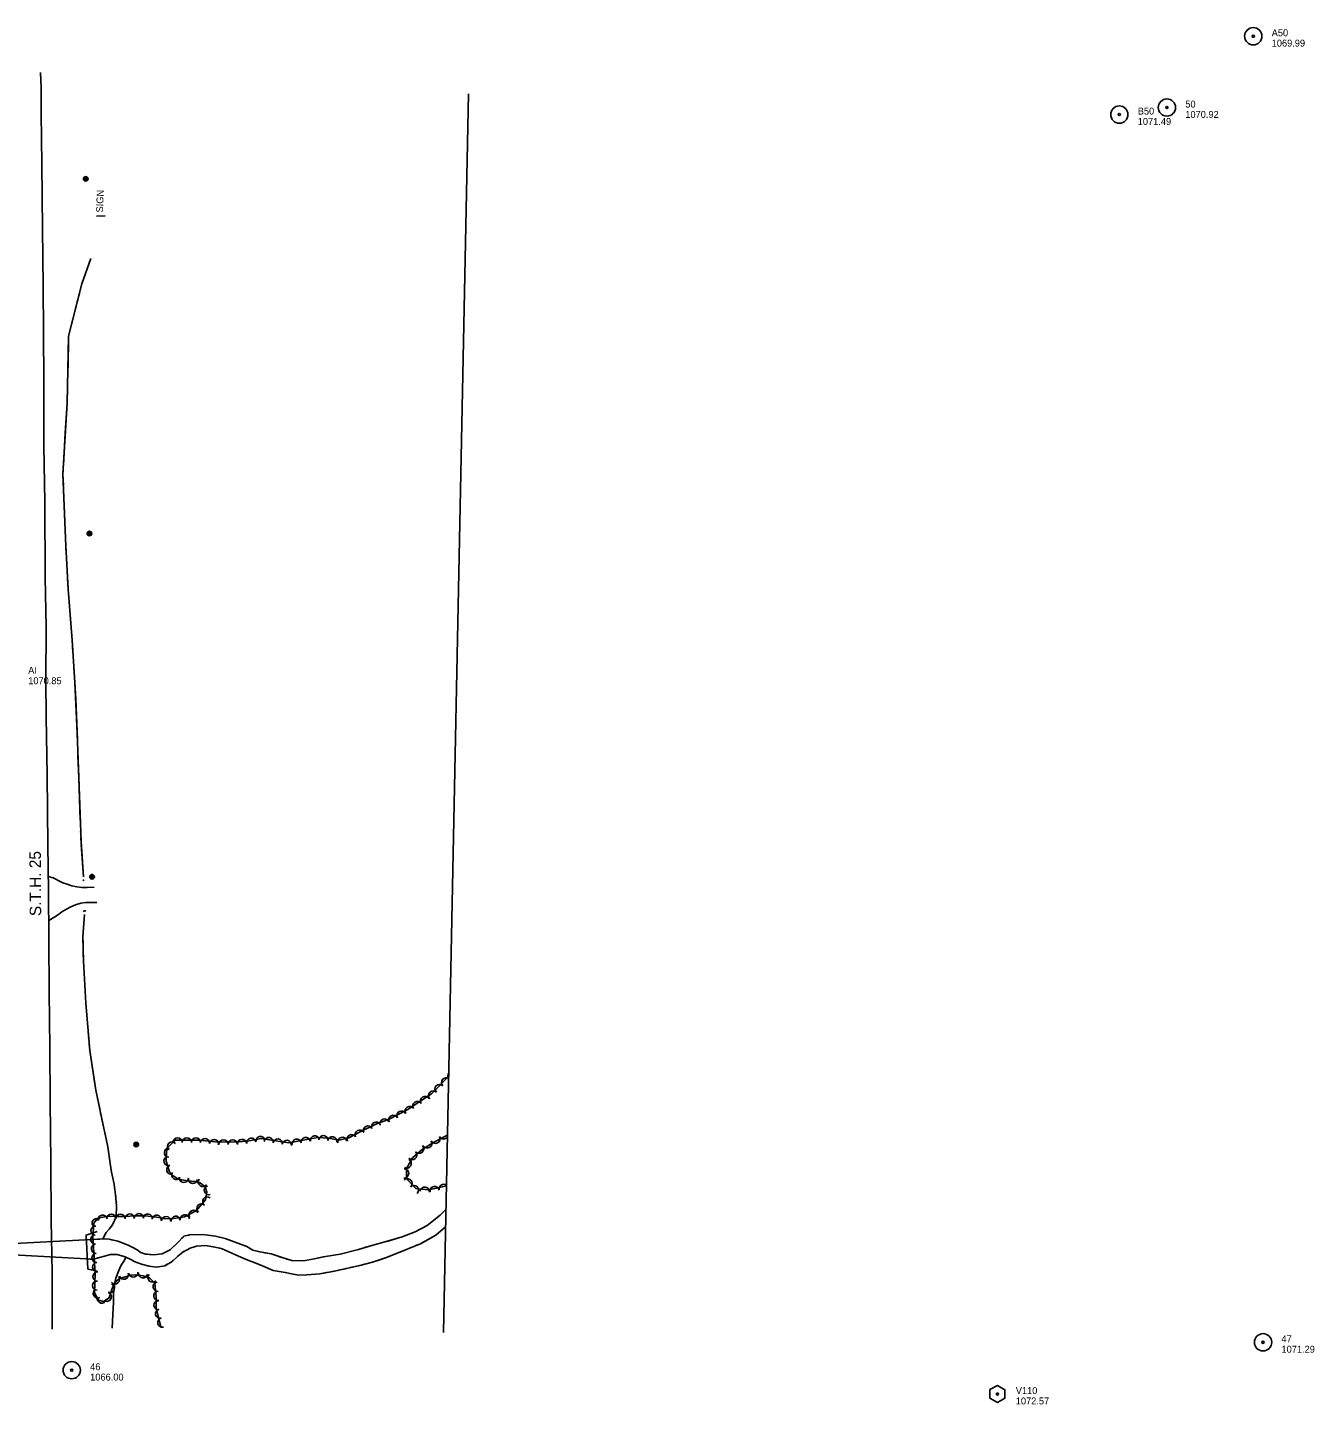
# Model space of a CAD drawing. Extents: x 296471 to 298842, y 32694 to 33905.
# Drawn here: x 297724 to 298842, y 32694 to 33889 of the extents above; entities that cross this region are included whole.
import ezdxf

# ---------------------------------------------------------------- set-up
doc = ezdxf.new("R2010")
doc.units = 0
for name, color, linetype in [('Level 11', 7, 'Continuous'), ('Level 14', 7, 'Continuous'), ('Level 15', 7, 'Continuous'), ('Level 17', 7, 'Continuous'), ('Level 18', 7, 'Continuous'), ('Level 19', 7, 'Continuous'), ('Level 4', 7, 'Continuous'), ('Level 5', 7, 'Continuous'), ('Level 6', 7, 'Continuous')]:
    doc.layers.add(name, color=color, linetype=linetype)

msp = doc.modelspace()

# ---------------------------------------------------------------- linework, layer by layer
at = {"layer": 'Level 11'}
msp.add_lwpolyline([(297745.7, 32759.5), (297745.6, 32808.7), (297744.8, 32853.7), (297744.4, 32904), (297743.9, 32957.3), (297743.6, 33003.6), (297743, 33052.3), (297742.7, 33098.1), (297742.4, 33139.8), (297741.7, 33179.5), (297741.4, 33240.2), (297740.4, 33290.9), (297740, 33322.6), (297740.3, 33368.7), (297739.6, 33412), (297739.2, 33477.2), (297738.3, 33526.1), (297738.3, 33583.2), (297737.8, 33665.2), (297737.1, 33714.6), (297736.6, 33770.6), (297736.1, 33814.6), (297736, 33837.2), (297735.4, 33850.4)], dxfattribs=at)
at = {"layer": 'Level 14'}
msp.add_line((297784.2, 33725.6), (297791.7, 33725.8), dxfattribs=at)
for centre, radius in [((297774.7, 33758), 2.02), ((297774.7, 33758), 1.52), ((297774.8, 33758), 1.01), ((297774.8, 33758.1), 0.502), ((297777.9, 33450.1), 2.02), ((297777.9, 33450.1), 1.52), ((297777.9, 33450.1), 1.01), ((297777.9, 33450.1), 0.502), ((297780.2, 33152.1), 2.02), ((297780.2, 33152.1), 1.52), ((297780.3, 33152.1), 1.01), ((297780.2, 33152.1), 0.502), ((297818.6, 32919.7), 2.02), ((297818.6, 32919.7), 1.52), ((297818.6, 32919.7), 1.01), ((297818.6, 32919.7), 0.502)]:
    msp.add_circle(centre, radius, dxfattribs=at)
at = {"layer": 'Level 15'}
msp.add_lwpolyline([(297784, 32809.9), (297776.7, 32811.6), (297775, 32841.1), (297784.6, 32844.2)], dxfattribs=at)
for centre, radius, start, end in [((297772.8, 33150), 0.795, 220.5288, 326.7683), ((297773.8, 33121.2), 1.37, 45.8398, 152.0794)]:
    msp.add_arc(centre, radius, start, end, dxfattribs=at)
at = {"layer": 'Level 17'}
for points in [[(297782.2, 33143.2), (297776.1, 33142.7), (297771.3, 33142.9), (297767.1, 33143.4), (297762.7, 33144.4), (297758.5, 33145.7), (297755, 33146.9), (297751.9, 33148.2), (297748.2, 33150.2), (297746.5, 33151.3), (297742.2, 33152.5)], [(297742.6, 33114.2), (297747.9, 33117.3), (297751, 33119.3), (297753.9, 33121.7), (297757.6, 33123.8), (297761.8, 33126), (297765.8, 33127.8), (297770.6, 33129.1), (297774.9, 33129.7), (297779.2, 33129.9), (297782.5, 33129.9), (297784.4, 33129.7)]]:
    msp.add_lwpolyline(points, dxfattribs=at)
at = {"layer": 'Level 18'}
for points in [[(298089.9, 32979), (298074.9, 32963.6), (298053.8, 32949.7), (298038.3, 32941.7), (298026.7, 32937.5), (298012.9, 32930.8), (298003.2, 32925.5), (297994.6, 32923.5), (297985.7, 32925.2), (297976.4, 32925.8), (297963.5, 32923.5), (297951.2, 32921.3), (297939.8, 32922.9), (297927.2, 32925), (297915.2, 32922.7), (297906.6, 32921.9), (297890, 32921.7), (297873.5, 32923.6), (297852.6, 32923.6), (297845.1, 32916.4), (297844.5, 32905.1), (297847.4, 32895.9), (297850.8, 32892.5), (297854.6, 32889.9), (297857.8, 32888.9), (297863.8, 32888.3), (297869.6, 32887.6), (297874, 32886.3), (297878.4, 32883), (297880, 32878.3), (297878.8, 32871.7), (297870.6, 32862), (297860.6, 32856.8), (297849.2, 32855.1), (297842.5, 32855.4), (297836.3, 32856.6), (297826.3, 32857.8), (297818.8, 32857.7), (297807.6, 32857.3), (297800.5, 32857.3), (297793.8, 32857.4), (297785.3, 32855.9), (297781.7, 32851.4), (297780.8, 32839.4), (297782, 32821.4), (297783, 32807.7), (297782.7, 32799.1), (297782.5, 32791), (297785.8, 32784.5), (297790.2, 32783.5), (297795, 32786.6), (297797.5, 32793.9), (297799.8, 32799.7), (297804.2, 32803.3), (297809.1, 32804.9), (297813.9, 32806.2), (297818.2, 32806.6), (297824.6, 32805.7), (297830, 32803.9), (297834.8, 32799.4), (297835.1, 32796.2), (297835.8, 32787.1), (297835.9, 32777.5), (297840.3, 32760.7)], [(298088, 32884), (298087.8, 32883.9), (298080.8, 32882.2), (298072, 32880.5), (298061.4, 32881.5), (298053.2, 32889.9), (298053.3, 32898.8), (298058.5, 32908.1), (298067.2, 32915.8), (298078.3, 32922.3), (298085.4, 32926), (298088.9, 32927.9)]]:
    msp.add_lwpolyline(points, dxfattribs=at)
for centre, radius, start, end in [((298093.1, 32979.4), 3.99, 142.7947, 214.8848), ((298082, 32967.9), 3.99, 45.8286, 225.8133), ((298087.6, 32973.6), 3.99, 55.0667, 225.8133), ((298062.7, 32953.1), 3.99, 33.3523, 213.337), ((298069.4, 32957.5), 3.99, 33.3523, 213.337), ((298076.4, 32962.2), 3.99, 45.8286, 225.8133), ((298041.8, 32941.1), 3.99, 27.3914, 207.3761), ((298048.9, 32944.8), 3.99, 27.3914, 207.3761), ((298056.1, 32948.7), 3.99, 33.3523, 213.337), ((298012.6, 32928.3), 3.99, 28.6819, 208.6666), ((298019.7, 32931.8), 3.99, 25.7904, 205.7751), ((298026.9, 32935.2), 3.99, 25.7904, 205.7751), ((298034.2, 32937.9), 3.99, 19.8828, 199.8675), ((297849.7, 32917.9), 3.99, 43.7975, 223.7821), ((297854.5, 32921.5), 3.99, 359.9336, 179.9183), ((297862.5, 32921.5), 3.99, 359.9336, 179.9183), ((297870.5, 32921.5), 3.99, 359.9336, 179.9183), ((297878.2, 32920.9), 3.99, 353.5497, 173.5344), ((297886.2, 32920), 3.99, 353.5497, 173.5344), ((297894.4, 32919.7), 3.99, 0.8438, 180.8284), ((297902.4, 32919.8), 3.99, 0.8438, 180.8284), ((297910.5, 32920.2), 3.99, 5.1973, 185.182), ((297918.6, 32921.2), 3.99, 10.8716, 190.8563), ((297926.5, 32922.7), 3.99, 10.8716, 190.8563), ((297933.6, 32921.8), 3.99, 350.5439, 170.5285), ((297941.5, 32920.6), 3.99, 351.7578, 171.7425), ((297949.4, 32919.4), 3.99, 351.7578, 171.7425), ((297958, 32920.4), 3.99, 10.0225, 190.0072), ((297965.8, 32921.8), 3.99, 10.3728, 190.3575), ((297973.7, 32923.2), 3.99, 10.3728, 190.3575), ((297981.1, 32923.4), 3.99, 356.1826, 176.1672), ((297988.8, 32922.5), 3.99, 349.1535, 169.1382), ((297997.5, 32922), 3.99, 13.0293, 193.014), ((298005.6, 32924.4), 3.99, 28.6819, 208.6666), ((298064.2, 32916), 4.06, 221.7032, 41.6879), ((298071.3, 32920.7), 4.06, 210.3064, 30.2911), ((298078.4, 32924.7), 4.06, 207.6497, 27.6344), ((298085.6, 32928.5), 4.06, 208.3577, 322.9908), ((297846.6, 32905.4), 3.99, 107.5699, 287.5546), ((297847, 32912.6), 3.99, 86.7553, 266.7399), ((298053.4, 32903.2), 4.06, 240.7011, 60.6858), ((298058.2, 32910.6), 4.06, 221.7032, 41.6879), ((297849, 32897.8), 3.99, 107.5699, 287.5546), ((297853.5, 32893.2), 3.99, 145.2965, 325.2812), ((298051.1, 32894.6), 4.06, 268.8817, 88.8664), ((297859.9, 32890.8), 3.99, 174.0309, 354.0156), ((297867.8, 32889.9), 3.99, 173.2863, 353.271), ((297876.4, 32887.2), 3.99, 142.6731, 322.6577), ((297881.6, 32880), 3.99, 108.4864, 288.471), ((298054.1, 32886), 4.06, 314.4349, 134.4196), ((298059.7, 32880.2), 4.06, 314.4349, 134.4196), ((298069.1, 32878.7), 4.06, 354.5144, 174.4991), ((298077.7, 32879.4), 4.06, 10.8715, 190.8562), ((298085.7, 32881.2), 4.06, 55.6508, 193.7913), ((297880.3, 32870.3), 3.99, 50.0078, 229.9925), ((297796.9, 32855.3), 3.99, 358.6336, 178.6183), ((297804.9, 32855.2), 3.99, 0.1213, 180.1059), ((297813, 32855.4), 3.99, 2.3923, 182.377), ((297820.9, 32855.7), 3.99, 0.2737, 180.2584), ((297828.6, 32855.4), 3.99, 353.3787, 173.3634), ((297860.8, 32854.7), 3.99, 8.6229, 188.6075), ((297868.5, 32858.6), 3.99, 27.5153, 207.4999), ((297875.2, 32864.1), 3.99, 50.0078, 229.9925), ((297783.3, 32844.9), 3.99, 85.9315, 265.9162), ((297784.3, 32851.4), 3.99, 51.4537, 231.4383), ((297789.4, 32854.5), 3.99, 10.003, 189.9877), ((297836.4, 32854.5), 3.99, 348.5183, 168.503), ((297844.5, 32853.2), 3.99, 357.4393, 177.424), ((297852.9, 32853.5), 3.99, 8.6229, 188.6075), ((297783, 32837.2), 3.99, 93.6921, 273.6767), ((297783.6, 32829.2), 3.99, 93.6921, 273.6767), ((297784.1, 32821.3), 3.99, 94.2545, 274.2392), ((297784.7, 32813.3), 3.99, 94.2545, 274.2392), ((297784.7, 32797.2), 3.99, 89.2131, 269.1978), ((297785, 32805.1), 3.99, 87.8802, 267.8648), ((297800.2, 32802.7), 3.99, 219.8648, 39.8495), ((297807.9, 32806.7), 3.99, 197.6434, 17.6281), ((297816.1, 32808.5), 3.99, 185.15, 5.1347), ((297824.5, 32807.8), 3.99, 172.4224, 352.4071), ((297832.8, 32804.1), 3.99, 136.9004, 316.8851), ((297837.2, 32796.2), 3.99, 94.4345, 274.4191), ((297785.2, 32790.4), 3.99, 116.8018, 296.7865), ((297793.1, 32787.5), 3.99, 250.791, 70.7757), ((297795.8, 32795.1), 3.99, 248.7799, 68.7645), ((297837.8, 32788.3), 3.99, 94.4345, 274.4191), ((297788.7, 32786), 3.99, 167.0407, 347.0253), ((297838, 32780.1), 3.99, 90.7993, 270.7839), ((297839.3, 32772.8), 3.99, 104.5322, 284.5169), ((297841.3, 32765.1), 3.99, 104.5322, 284.5169)]:
    msp.add_arc(centre, radius, start, end, dxfattribs=at)
at = {"layer": 'Level 19'}
for points in [[(297772.8, 33152.1), (297770.7, 33182.6), (297768.7, 33238.2), (297767.4, 33276.9), (297765.4, 33320.7), (297762.9, 33357.6), (297759.4, 33401.7), (297757.5, 33439.3), (297754.9, 33501.7), (297758.6, 33563.3), (297759.9, 33621.5), (297771.5, 33666.9), (297779.3, 33688.8)], [(297770.3, 33662.3), (297771.5, 33666.9), (297779.3, 33688.8)], [(297767.4, 33651.1), (297767.9, 33653)], [(297768.9, 33656.7), (297769.3, 33658.6)], [(297759.8, 33614.4), (297759.9, 33621.5), (297765.1, 33641.8)], [(297766, 33645.5), (297766.5, 33647.4)], [(297759.1, 33586.5), (297759.8, 33614.4)], [(297758.8, 33574.9), (297758.9, 33576.8)], [(297759, 33580.7), (297759, 33582.6)], [(297757, 33537.3), (297758.6, 33563.3), (297758.6, 33565.2)], [(297758.7, 33569.1), (297758.8, 33571)], [(297755.4, 33509.4), (297757, 33537.3)], [(297755.1, 33503.6), (297755.2, 33505.5)], [(297755.1, 33497.8), (297755, 33499.8)], [(297755.3, 33492.1), (297755.3, 33494)], [(297756.6, 33460.3), (297755.5, 33488.2)], [(297757.8, 33432.3), (297757.5, 33439.3), (297756.6, 33460.3)], [(297758.1, 33426.5), (297758, 33428.5)], [(297758.4, 33420.8), (297758.3, 33422.7)], [(297758.7, 33415), (297758.6, 33416.9)], [(297760.9, 33383.2), (297759.4, 33401.7), (297758.9, 33411.1)], [(297763, 33355.3), (297762.9, 33357.6), (297760.9, 33383.2)], [(297763.4, 33349.6), (297763.3, 33351.5)], [(297763.8, 33343.8), (297763.7, 33345.7)], [(297764.2, 33338), (297764.1, 33339.9)], [(297766.1, 33306.2), (297765.4, 33320.7), (297764.5, 33334.2)], [(297767.3, 33278.3), (297766.1, 33306.2)], [(297767.5, 33272.5), (297767.5, 33274.4)], [(297767.7, 33266.7), (297767.7, 33268.7)], [(297767.9, 33260.9), (297767.9, 33262.9)], [(297769, 33229.1), (297768.7, 33238.2), (297768, 33257.1)], [(297770, 33201.2), (297769, 33229.1)], [(297770.2, 33195.4), (297770.1, 33197.3)], [(297770.4, 33189.6), (297770.3, 33191.5)], [(297770.6, 33183.8), (297770.6, 33185.8)], [(297772.8, 33152.1), (297770.9, 33180)], [(297789.7, 32837.7), (297792.6, 32843.4), (297795.1, 32846.2), (297798.1, 32850.1), (297801.1, 32856.9), (297801.6, 32866.5), (297800.7, 32875.9), (297799.3, 32885.2), (297797.2, 32895.6), (297795.9, 32903.1), (297793.8, 32917.6), (297789.6, 32938), (297783.4, 32966.9), (297778.2, 33001.3), (297774.8, 33042.3), (297772.7, 33078.9), (297772.2, 33100.1), (297773.8, 33119.5)], [(297772.4, 33093.5), (297772.2, 33100.1), (297773.8, 33119.5)], [(297772.5, 33088.1), (297772.5, 33089.9)], [(297772.6, 33082.7), (297772.6, 33084.5)], [(297772.8, 33077.3), (297772.7, 33078.9), (297772.7, 33079.1)], [(297774.5, 33047.7), (297773, 33073.7)], [(297776.5, 33021.7), (297774.8, 33042.3), (297774.5, 33047.7)], [(297776.9, 33016.3), (297776.8, 33018.1)], [(297777.4, 33010.9), (297777.2, 33012.7)], [(297777.8, 33005.6), (297777.7, 33007.4)], [(297782, 32976.2), (297778.2, 33001.3), (297778.1, 33002)], [(297786.9, 32950.6), (297783.4, 32966.9), (297782, 32976.2)], [(297788, 32945.3), (297787.6, 32947.1)], [(297789.1, 32940.1), (297788.7, 32941.8)], [(297790.2, 32934.8), (297789.9, 32936.6)], [(297795.6, 32905.6), (297793.8, 32917.6), (297790.9, 32931.3)], [(297800.1, 32880), (297799.3, 32885.2), (297797.2, 32895.6), (297795.9, 32903.1), (297795.6, 32905.6)], [(297800.9, 32874.7), (297800.7, 32875.9), (297800.7, 32876.5)], [(297801.4, 32869.3), (297801.2, 32871.1)], [(297789.7, 32837.7), (297792.6, 32843.4), (297795.1, 32846.2), (297798.1, 32850.1), (297801.1, 32856.9), (297801.3, 32860.4)], [(297801.5, 32863.9), (297801.6, 32865.7)], [(298087.5, 32863.3), (298082.6, 32858.5), (298071.1, 32849.5), (298060.8, 32844), (298049.5, 32839.6), (298035.7, 32835.4), (298023.3, 32832.1), (298011.7, 32828.7), (297995.8, 32824.6), (297983, 32822.5), (297973.2, 32820.4), (297964.2, 32818.8), (297953.7, 32818.9), (297946.1, 32821.2), (297935.7, 32824.8), (297925.8, 32826.4), (297919.9, 32828), (297914.6, 32831.1), (297895.7, 32838.2)], [(298087.5, 32863.3), (298082.6, 32858.5), (298071.1, 32849.5), (298066.2, 32846.9)], [(297893.1, 32829.2), (297898.4, 32826.9), (297907.5, 32822.8), (297915.4, 32819.4), (297921, 32817.3), (297928.9, 32814), (297937.5, 32810.4), (297948, 32808.6), (297954.9, 32807.2), (297959.8, 32806.3), (297966.6, 32806.5), (297978, 32807.4), (297989.2, 32809.6), (298001.1, 32812), (298012.7, 32814.7), (298023.8, 32817.6), (298035.9, 32821.5), (298048.2, 32826.6), (298065.3, 32833.4), (298078.6, 32841), (298087.2, 32848.2)], [(298066.2, 32846.9), (298060.8, 32844), (298049.5, 32839.6), (298036.1, 32835.5)], [(298070.9, 32836.6), (298078.6, 32841), (298087.2, 32848.2)], [(297690.4, 32832.5), (297790.9, 32837.7), (297795, 32837.4), (297802.5, 32835.8), (297807.2, 32834.1), (297812.2, 32832), (297816.9, 32829.7), (297820.4, 32827.6), (297822.4, 32826.1), (297822.5, 32826), (297825.9, 32824.7), (297833.5, 32823.8), (297841.2, 32824.8), (297848, 32828.4), (297854.4, 32834.3), (297860, 32840), (297864.8, 32841.2), (297876.5, 32841.6), (297887.4, 32840.2), (297895.7, 32838.2)], [(297775.3, 32836.9), (297781.3, 32837.2)], [(297785.1, 32837.4), (297787, 32837.5)], [(297790.7, 32837.7), (297790.9, 32837.7), (297792.6, 32837.6)], [(297796.3, 32837.1), (297798.2, 32836.7)], [(297801.9, 32835.9), (297802.5, 32835.8), (297807.2, 32834.1), (297812.2, 32832), (297816.9, 32829.7), (297820.4, 32827.6), (297822.4, 32826.1), (297822.5, 32826), (297825.9, 32824.7), (297826.5, 32824.6)], [(297854.3, 32834.3), (297854.4, 32834.3), (297855.7, 32835.6)], [(297858.3, 32838.3), (297859.6, 32839.6)], [(297863.2, 32840.8), (297864.8, 32841.2), (297865, 32841.2)], [(297868.8, 32841.4), (297876.5, 32841.6), (297887.4, 32840.2), (297895.7, 32838.2)], [(297925.7, 32826.4), (297919.9, 32828), (297914.6, 32831.1), (297895.7, 32838.2)], [(298066.3, 32834), (298067.8, 32834.9)], [(297685.5, 32825.4), (297780.4, 32820.2), (297782.7, 32820.6), (297786.8, 32821.6), (297790.9, 32822.9), (297796.3, 32824.1), (297802, 32824.2), (297808.9, 32822.3), (297814.4, 32819.5), (297816.8, 32818)], [(297785.1, 32821.2), (297786.8, 32821.6), (297790.9, 32822.9), (297796.3, 32824.1), (297802, 32824.2), (297808.9, 32822.3), (297814.4, 32819.5), (297816.8, 32818)], [(297816.8, 32818), (297823.3, 32815.8), (297829.9, 32814), (297836.1, 32813.3), (297843.5, 32814.5), (297849.7, 32818.2), (297854.6, 32822.7), (297859, 32826.2), (297865.3, 32829.7), (297870.9, 32831.4), (297878.9, 32831.9), (297886.8, 32830.7), (297891.1, 32829.7), (297893.1, 32829.2)], [(297826.5, 32824.6), (297833.5, 32823.8), (297841.2, 32824.8), (297848, 32828.4), (297851.6, 32831.7)], [(297853.8, 32821.9), (297854.6, 32822.7), (297855.3, 32823.3)], [(297858.5, 32825.9), (297859, 32826.2), (297860.3, 32827)], [(297863.9, 32828.9), (297865.3, 32829.7), (297870.9, 32831.4), (297878.9, 32831.9), (297886.8, 32830.7), (297891.1, 32829.7), (297893.1, 32829.2)], [(297893.1, 32829.2), (297898.4, 32826.9), (297907.5, 32822.8), (297915.4, 32819.4), (297916.6, 32818.9)], [(297932.2, 32825.4), (297930.1, 32825.7)], [(297938.7, 32823.8), (297936.6, 32824.5)], [(298012.5, 32828.9), (298011.7, 32828.7), (297995.8, 32824.6), (297983, 32822.5), (297981, 32822.1)], [(298018.9, 32830.8), (298016.8, 32830.2)], [(298025.3, 32832.7), (298023.3, 32832.1), (298023.2, 32832.1)], [(298029.2, 32819.3), (298035.9, 32821.5), (298048.2, 32826.6), (298053.2, 32828.6)], [(298031.8, 32834.3), (298029.6, 32833.8)], [(298056.4, 32829.9), (298058.1, 32830.5)], [(298061.4, 32831.9), (298063, 32832.5)], [(297778.3, 32820.3), (297780.4, 32820.2), (297780.6, 32820.2)], [(297797.8, 32760.3), (297798.7, 32777.8), (297798.8, 32782.4), (297798.9, 32790), (297799.9, 32799.5), (297800.9, 32803.8), (297801.9, 32806.6), (297803.5, 32810.2), (297804.9, 32813.7), (297806.1, 32815.9), (297807.5, 32817.8), (297807.7, 32818.1), (297809.6, 32822)], [(297800.2, 32801), (297800.9, 32803.8), (297801.9, 32806.6), (297803.5, 32810.2), (297804.9, 32813.7), (297806.1, 32815.9), (297807.5, 32817.8), (297807.7, 32818.1), (297809.6, 32822)], [(297816.8, 32818), (297823.3, 32815.8), (297829.9, 32814), (297836.1, 32813.3), (297843.5, 32814.5), (297845.6, 32815.8)], [(297849.1, 32817.9), (297849.7, 32818.2), (297850.7, 32819.2)], [(297919.9, 32817.7), (297921, 32817.3), (297921.6, 32817.1)], [(297924.8, 32815.7), (297926.5, 32815.1)], [(297929.7, 32813.7), (297931.4, 32813)], [(297934.6, 32811.6), (297937.5, 32810.4), (297948, 32808.6), (297954.9, 32807.2), (297959.7, 32806.3)], [(297945, 32821.6), (297942.9, 32822.3)], [(297981, 32822.1), (297973.2, 32820.4), (297964.2, 32818.8), (297953.7, 32818.9), (297949.2, 32820.2)], [(297993.9, 32810.5), (297995.7, 32810.9)], [(297999.1, 32811.6), (298000.9, 32812)], [(298004.3, 32812.8), (298012.7, 32814.7), (298023.8, 32817.6), (298029.2, 32819.3)], [(297959.7, 32806.3), (297959.8, 32806.3), (297966.6, 32806.5), (297978, 32807.4), (297985.2, 32808.8)], [(297988.7, 32809.5), (297989.2, 32809.6), (297990.5, 32809.8)], [(297798.8, 32786.6), (297798.9, 32788.2)], [(297799.1, 32791.4), (297799.2, 32793)], [(297799.5, 32796.2), (297799.7, 32797.8)], [(297797.8, 32760.3), (297798.7, 32777.8), (297798.8, 32782.4), (297798.8, 32783.4)]]:
    msp.add_lwpolyline(points, dxfattribs=at)
at = {"layer": 'Level 4'}
msp.add_lwpolyline([(298085.4, 32756.4), (298107.2, 33831.8)], dxfattribs=at)
at = {"layer": 'Level 5'}
msp.add_lwpolyline([(298559.9, 32706.9), (298559.9, 32699.5), (298566.4, 32695.8), (298572.8, 32699.4), (298572.8, 32706.8), (298566.3, 32710.5)], close=True, dxfattribs=at)
msp.add_circle((298566.3, 32703.1), 0.871, dxfattribs=at)
at = {"layer": 'Level 6'}
for centre, radius in [((298788.5, 33881.8), 7.5), ((298788.5, 33881.8), 0.96), ((298713.5, 33819.9), 7.5), ((298672.2, 33813.8), 7.5), ((298713.5, 33819.9), 0.96), ((298672.2, 33813.8), 0.96), ((298797, 32748), 7.5), ((298797, 32748), 0.96), ((297762.6, 32723.8), 7.5), ((297762.6, 32723.8), 0.96)]:
    msp.add_circle(centre, radius, dxfattribs=at)

# ---------------------------------------------------------------- texts
at = {"layer": 'Level 11'}
msp.add_text('S.T.H. 25', height=10, rotation=90.2934, dxfattribs=at).set_placement((297736.1, 33118))
at = {"layer": 'Level 14'}
msp.add_text('SIGN', height=6, rotation=87.9573, dxfattribs=at).set_placement((297789.7, 33728.7))
at = {"layer": 'Level 5'}
for s, p in [('V110', (298582.3, 32703.1)), ('1072.57', (298582.3, 32694.1))]:
    msp.add_text(s, height=6, dxfattribs=at).set_placement(p)
at = {"layer": 'Level 6'}
for s, p in [('A50', (298804.5, 33881.8)), ('1069.99', (298804.5, 33872.8)), ('B50', (298688.2, 33813.8)), ('50', (298729.5, 33819.9)), ('1070.92', (298729.5, 33810.9)), ('1071.49', (298688.2, 33804.8)), ('AI', (297724.8, 33328.3)), ('1070.85', (297724.8, 33319.3)), ('47', (298813, 32748)), ('1071.29', (298813, 32739)), ('46', (297778.6, 32723.8)), ('1066.00', (297778.6, 32714.8))]:
    msp.add_text(s, height=6, dxfattribs=at).set_placement(p)

doc.saveas('drawing.dxf')
